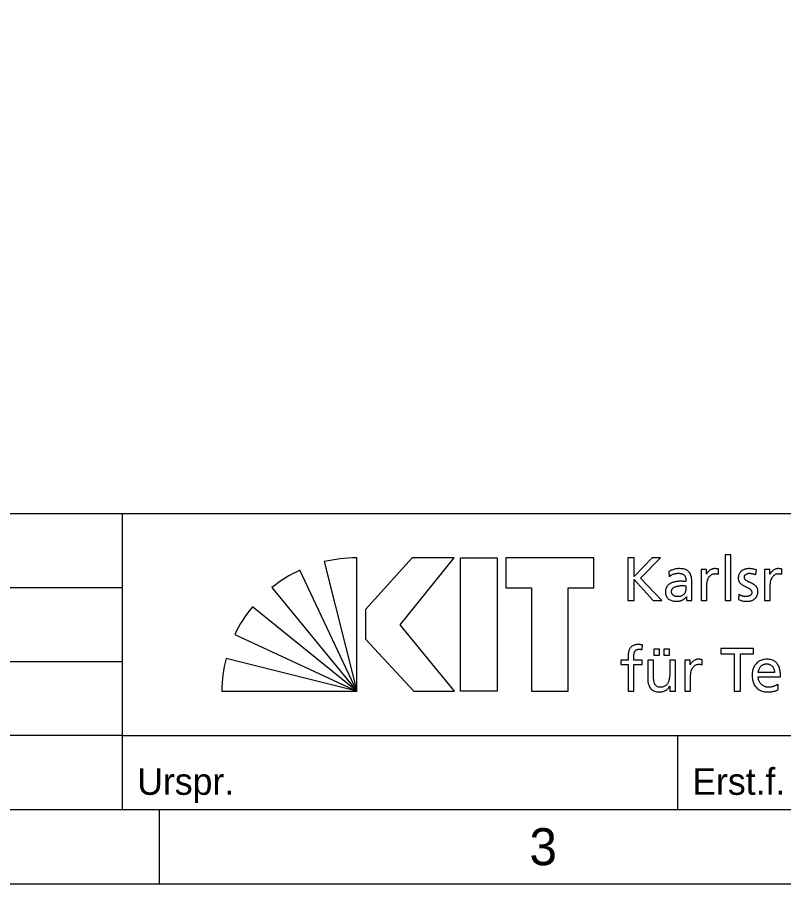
# Model space of a CAD drawing. Extents: x 0 to 420, y 0 to 297.
# Drawn here: x 97.9 to 149.7, y 0 to 58.5 of the extents above; entities that cross this region are included whole.
import ezdxf

# ---------------------------------------------------------------- set-up
doc = ezdxf.new("R2010")
doc.units = 0
doc.layers.add('90_Plankopf', color=7, linetype='Continuous')

msp = doc.modelspace()

# ---------------------------------------------------------------- linework, layer by layer
at = {"layer": '90_Plankopf'}
for p, q in [((5, 25), (415, 25)), ((105, 5), (105, 25)), ((118.621, 21.747), (120.828, 13.001)), ((120.828, 13.001), (120.828, 21.999)), ((139.156, 22.001), (139.156, 19.12)), ((120.828, 13.001), (116.98, 21.167)), ((141.926, 21.076), (141.947, 20.746)), ((145.273, 20.899), (145.273, 21.245)), ((147.804, 20.853), (147.837, 21.192)), ((149.558, 20.899), (149.558, 21.245)), ((5, 20), (105, 20)), ((115.091, 20), (120.828, 13.001)), ((143.077, 20.123), (143.077, 19.937)), ((143.465, 19.533), (143.465, 20.404)), ((146.644, 19.533), (146.624, 19.186)), ((139.156, 19.12), (139.569, 19.12)), ((140.852, 19.12), (141.455, 19.12)), ((120.828, 13.001), (113.78, 18.7)), ((112.587, 16.828), (120.828, 13.001)), ((140.12, 15.807), (140.137, 16.121)), ((5, 15), (105, 15)), ((120.828, 13.001), (112.004, 15.202)), ((144.174, 14.779), (144.174, 15.126)), ((149.053, 14.255), (147.963, 14.255)), ((147.963, 13.967), (149.466, 13.967)), ((149.304, 13.088), (149.304, 13.475)), ((111.711, 13.001), (120.828, 13.001)), ((105, 10), (5, 10)), ((105, 10), (225, 10)), ((142.5, 10), (142.5, 5)), ((107.5, 0), (107.5, 5))]:
    msp.add_line(p, q, dxfattribs=at)
for points in [[(0, 0), (420, 0), (420, 297), (0, 297)], [(5, 5), (415, 5), (415, 292), (5, 292)], [(127.413, 22.001), (124.583, 22.001), (121.42, 18.513), (121.42, 16.506), (124.685, 13.001), (127.432, 13.001), (123.769, 17.477)], [(130.317, 22.001), (130.317, 13.001), (127.848, 13.001), (127.848, 22.001)], [(130.909, 22.001), (130.909, 19.975), (132.648, 19.975), (132.648, 13.001), (135.118, 13.001), (135.118, 19.975), (136.856, 19.975), (136.856, 22.001)]]:
    msp.add_lwpolyline(points, close=True, dxfattribs=at)
for points in [[(141.455, 19.12), (139.994, 20.639), (141.348, 22.001), (140.799, 22.001), (139.569, 20.734), (139.569, 22.001), (139.156, 22.001)], [(145.728, 19.12), (146.115, 19.12), (146.115, 22.215), (145.728, 22.215), (145.728, 19.12)], [(144.469, 20.899), (144.46, 20.899), (144.46, 21.225), (144.097, 21.225), (144.097, 19.12), (144.485, 19.12), (144.485, 20.078)], [(148.754, 20.899), (148.745, 20.899), (148.745, 21.225), (148.382, 21.225), (148.382, 19.12), (148.77, 19.12), (148.77, 20.078)], [(139.569, 19.12), (139.569, 20.532), (140.852, 19.12)], [(143.11, 19.393), (143.118, 19.393), (143.118, 19.12), (143.482, 19.12)], [(140.901, 15.84), (140.901, 15.427), (141.289, 15.427), (141.289, 15.84), (140.901, 15.84)], [(141.578, 15.84), (141.578, 15.427), (141.966, 15.427), (141.966, 15.84), (141.578, 15.84)], [(146.337, 13.001), (146.75, 13.001), (146.75, 15.518), (147.645, 15.518), (147.645, 15.881), (145.441, 15.881), (145.441, 15.518), (146.337, 15.518), (146.337, 13.001)], [(139.171, 15.3), (139.171, 15.105), (138.676, 15.105), (138.676, 14.792), (139.171, 14.792), (139.171, 13.001), (139.559, 13.001), (139.559, 14.792), (140.116, 14.792), (140.116, 15.105), (139.559, 15.105), (139.559, 15.332)], [(140.889, 14.016), (140.889, 15.105), (140.5, 15.105), (140.5, 13.855)], [(142.362, 13.001), (142.362, 15.105), (141.974, 15.105), (141.974, 14.132)], [(143.369, 14.779), (143.361, 14.779), (143.361, 15.105), (142.998, 15.105), (142.998, 13.001), (143.386, 13.001), (143.386, 13.958)], [(141.978, 13.335), (141.986, 13.335), (141.986, 13.001), (142.362, 13.001)]]:
    msp.add_lwpolyline(points, dxfattribs=at)
for centre, start, end in [((120.795, 12.471), 89.80527, 103.18947), ((121.008, 12.532), 115.01261, 128.3968), ((121.163, 12.677), 140.78977, 154.17397), ((121.238, 12.852), 165.72225, 179.10644)]:
    msp.add_arc(centre, 9.528, start, end, dxfattribs=at)
for points in [[(143.465, 20.404), (143.466, 20.595), (143.437, 20.755), (143.38, 20.884), (143.322, 21.014), (143.231, 21.111), (143.106, 21.176), (142.982, 21.241), (142.819, 21.274), (142.619, 21.274), (142.485, 21.274), (142.361, 21.255), (142.244, 21.219), (142.129, 21.183), (142.023, 21.135), (141.926, 21.076)], [(145.273, 21.245), (145.246, 21.251), (145.22, 21.256), (145.196, 21.261), (145.171, 21.265), (145.145, 21.268), (145.116, 21.27), (145.088, 21.273), (145.055, 21.274), (145.017, 21.274), (144.942, 21.274), (144.869, 21.258), (144.799, 21.226), (144.728, 21.194), (144.664, 21.15), (144.607, 21.093), (144.55, 21.037), (144.503, 20.972), (144.469, 20.899)], [(147.837, 21.192), (147.761, 21.215), (147.684, 21.235), (147.606, 21.25), (147.528, 21.266), (147.444, 21.274), (147.354, 21.274), (147.249, 21.274), (147.152, 21.261), (147.062, 21.235), (146.972, 21.208), (146.894, 21.168), (146.826, 21.115), (146.759, 21.061), (146.706, 20.994), (146.669, 20.913), (146.631, 20.831), (146.612, 20.736), (146.611, 20.627), (146.612, 20.543), (146.629, 20.47), (146.662, 20.408), (146.694, 20.347), (146.738, 20.294), (146.792, 20.249), (146.846, 20.204), (146.906, 20.164), (146.97, 20.129), (147.035, 20.095), (147.1, 20.062), (147.164, 20.031), (147.229, 20.001), (147.289, 19.969), (147.342, 19.936), (147.397, 19.905), (147.44, 19.868), (147.473, 19.827), (147.505, 19.787), (147.523, 19.74), (147.523, 19.686), (147.523, 19.629), (147.51, 19.582), (147.486, 19.542), (147.463, 19.504), (147.431, 19.473), (147.392, 19.45), (147.353, 19.426), (147.31, 19.41), (147.264, 19.4), (147.218, 19.389), (147.172, 19.384), (147.127, 19.384), (147.089, 19.384), (147.042, 19.39), (146.986, 19.401), (146.93, 19.412), (146.873, 19.428), (146.813, 19.45), (146.752, 19.472), (146.696, 19.5), (146.644, 19.533)], [(149.558, 21.245), (149.531, 21.251), (149.505, 21.256), (149.481, 21.261), (149.456, 21.265), (149.429, 21.268), (149.401, 21.27), (149.373, 21.273), (149.34, 21.274), (149.302, 21.274), (149.227, 21.274), (149.154, 21.258), (149.084, 21.226), (149.013, 21.194), (148.949, 21.15), (148.892, 21.093), (148.835, 21.037), (148.789, 20.972), (148.754, 20.899)], [(141.947, 20.746), (141.999, 20.79), (142.059, 20.829), (142.126, 20.86), (142.193, 20.893), (142.263, 20.917), (142.336, 20.935), (142.41, 20.952), (142.484, 20.961), (142.557, 20.961), (142.686, 20.961), (142.788, 20.94), (142.865, 20.9), (142.941, 20.858), (142.995, 20.797), (143.028, 20.716), (143.062, 20.634), (143.078, 20.533), (143.077, 20.412)], [(144.485, 20.078), (144.486, 20.254), (144.51, 20.407), (144.556, 20.535), (144.604, 20.663), (144.67, 20.762), (144.756, 20.831), (144.841, 20.9), (144.942, 20.935), (145.058, 20.936), (145.092, 20.936), (145.127, 20.934), (145.164, 20.928), (145.202, 20.923), (145.237, 20.913), (145.273, 20.899)], [(146.624, 19.186), (146.713, 19.14), (146.807, 19.109), (146.905, 19.093), (147.002, 19.077), (147.101, 19.069), (147.201, 19.071), (147.296, 19.071), (147.387, 19.084), (147.474, 19.11), (147.562, 19.136), (147.64, 19.177), (147.71, 19.23), (147.778, 19.284), (147.833, 19.352), (147.874, 19.435), (147.915, 19.517), (147.935, 19.615), (147.936, 19.727), (147.935, 19.822), (147.918, 19.904), (147.886, 19.97), (147.853, 20.037), (147.809, 20.093), (147.755, 20.14), (147.701, 20.186), (147.642, 20.225), (147.577, 20.259), (147.512, 20.292), (147.447, 20.323), (147.383, 20.351), (147.318, 20.38), (147.258, 20.41), (147.205, 20.441), (147.15, 20.473), (147.107, 20.509), (147.074, 20.551), (147.042, 20.593), (147.025, 20.644), (147.024, 20.705), (147.025, 20.763), (147.042, 20.811), (147.076, 20.849), (147.11, 20.886), (147.155, 20.915), (147.211, 20.933), (147.267, 20.952), (147.329, 20.961), (147.395, 20.961), (147.419, 20.961), (147.449, 20.957), (147.485, 20.952), (147.522, 20.945), (147.56, 20.937), (147.601, 20.927), (147.642, 20.917), (147.68, 20.906), (147.716, 20.893), (147.752, 20.88), (147.781, 20.867), (147.804, 20.853)], [(148.77, 20.078), (148.771, 20.254), (148.795, 20.407), (148.841, 20.535), (148.889, 20.663), (148.955, 20.762), (149.041, 20.831), (149.126, 20.9), (149.227, 20.935), (149.344, 20.936), (149.377, 20.936), (149.412, 20.934), (149.449, 20.928), (149.486, 20.923), (149.522, 20.913), (149.558, 20.899)], [(143.077, 20.412), (143.027, 20.415), (142.98, 20.417), (142.936, 20.417), (142.893, 20.419), (142.849, 20.42), (142.806, 20.42), (142.762, 20.42), (142.715, 20.42), (142.664, 20.42), (142.583, 20.42), (142.498, 20.413), (142.409, 20.399), (142.32, 20.384), (142.233, 20.361), (142.147, 20.328), (142.062, 20.296), (141.985, 20.253), (141.915, 20.199), (141.846, 20.146), (141.791, 20.08), (141.75, 20.002), (141.709, 19.924), (141.688, 19.832), (141.686, 19.727), (141.688, 19.575), (141.721, 19.45), (141.786, 19.353), (141.851, 19.256), (141.941, 19.185), (142.056, 19.139), (142.172, 19.093), (142.306, 19.071), (142.458, 19.071), (142.547, 19.071), (142.627, 19.082), (142.697, 19.103), (142.768, 19.124), (142.83, 19.15), (142.883, 19.183), (142.937, 19.216), (142.982, 19.252), (143.02, 19.288), (143.057, 19.325), (143.087, 19.359), (143.11, 19.393)], [(143.077, 19.937), (143.077, 19.832), (143.055, 19.737), (143.01, 19.655), (142.967, 19.571), (142.9, 19.506), (142.814, 19.458), (142.727, 19.41), (142.619, 19.385), (142.491, 19.384), (142.447, 19.384), (142.401, 19.392), (142.355, 19.406), (142.31, 19.421), (142.267, 19.443), (142.229, 19.472), (142.19, 19.501), (142.159, 19.537), (142.136, 19.579), (142.112, 19.622), (142.1, 19.671), (142.099, 19.727), (142.101, 19.8), (142.119, 19.862), (142.155, 19.912), (142.191, 19.961), (142.238, 20), (142.296, 20.029), (142.354, 20.059), (142.416, 20.081), (142.482, 20.096), (142.548, 20.11), (142.612, 20.12), (142.673, 20.125), (142.734, 20.13), (142.786, 20.132), (142.83, 20.131), (142.871, 20.131), (142.912, 20.13), (142.953, 20.127), (142.995, 20.125), (143.036, 20.124), (143.077, 20.123)], [(143.482, 19.12), (143.479, 19.14), (143.476, 19.168), (143.473, 19.201), (143.471, 19.236), (143.469, 19.28), (143.468, 19.334), (143.466, 19.387), (143.465, 19.454), (143.465, 19.533)], [(140.137, 16.121), (140.098, 16.127), (140.057, 16.133), (140.014, 16.138), (139.972, 16.143), (139.926, 16.146), (139.877, 16.146), (139.735, 16.145), (139.617, 16.125), (139.525, 16.085), (139.433, 16.046), (139.361, 15.989), (139.309, 15.914), (139.257, 15.84), (139.221, 15.751), (139.201, 15.647), (139.18, 15.544), (139.171, 15.428), (139.171, 15.3)], [(139.559, 15.332), (139.559, 15.404), (139.563, 15.47), (139.571, 15.531), (139.579, 15.591), (139.596, 15.644), (139.622, 15.689), (139.647, 15.734), (139.685, 15.769), (139.735, 15.794), (139.785, 15.819), (139.851, 15.832), (139.935, 15.832), (139.968, 15.832), (140.002, 15.83), (140.035, 15.825), (140.069, 15.821), (140.097, 15.815), (140.12, 15.807)], [(144.174, 15.126), (144.147, 15.132), (144.121, 15.136), (144.097, 15.141), (144.072, 15.145), (144.045, 15.149), (144.017, 15.151), (143.989, 15.154), (143.956, 15.155), (143.918, 15.155), (143.843, 15.154), (143.77, 15.138), (143.699, 15.106), (143.629, 15.074), (143.565, 15.031), (143.508, 14.974), (143.45, 14.918), (143.404, 14.853), (143.369, 14.779)], [(143.386, 13.958), (143.386, 14.135), (143.41, 14.288), (143.457, 14.416), (143.505, 14.544), (143.571, 14.643), (143.656, 14.711), (143.742, 14.781), (143.843, 14.816), (143.959, 14.816), (143.993, 14.817), (144.028, 14.815), (144.065, 14.809), (144.102, 14.804), (144.138, 14.794), (144.174, 14.779)], [(149.466, 13.967), (149.466, 14.136), (149.45, 14.294), (149.419, 14.438), (149.388, 14.582), (149.336, 14.707), (149.265, 14.815), (149.192, 14.922), (149.097, 15.005), (148.978, 15.064), (148.859, 15.124), (148.711, 15.154), (148.537, 15.155), (148.388, 15.154), (148.253, 15.128), (148.132, 15.077), (148.011, 15.024), (147.907, 14.951), (147.821, 14.856), (147.734, 14.762), (147.668, 14.65), (147.621, 14.519), (147.575, 14.39), (147.551, 14.247), (147.55, 14.09), (147.55, 13.918), (147.572, 13.763), (147.616, 13.623), (147.659, 13.483), (147.726, 13.364), (147.815, 13.264), (147.905, 13.164), (148.018, 13.087), (148.155, 13.033), (148.292, 12.979), (148.454, 12.952), (148.64, 12.951), (148.755, 12.952), (148.853, 12.96), (148.934, 12.975), (149.014, 12.99), (149.084, 13.008), (149.144, 13.028), (149.202, 13.049), (149.256, 13.069), (149.304, 13.088)], [(147.963, 14.255), (147.97, 14.324), (147.986, 14.393), (148.011, 14.462), (148.035, 14.53), (148.069, 14.593), (148.114, 14.651), (148.159, 14.708), (148.216, 14.753), (148.284, 14.788), (148.352, 14.823), (148.434, 14.841), (148.528, 14.841), (148.612, 14.841), (148.687, 14.825), (148.751, 14.795), (148.817, 14.765), (148.871, 14.723), (148.916, 14.669), (148.961, 14.616), (148.995, 14.553), (149.018, 14.483), (149.041, 14.412), (149.053, 14.337), (149.053, 14.255)], [(141.974, 14.132), (141.974, 14.003), (141.962, 13.886), (141.936, 13.78), (141.911, 13.674), (141.872, 13.583), (141.82, 13.506), (141.768, 13.429), (141.701, 13.37), (141.62, 13.328), (141.54, 13.286), (141.444, 13.266), (141.334, 13.265), (141.222, 13.272), (141.133, 13.303), (141.068, 13.36), (141.003, 13.416), (140.957, 13.499), (140.929, 13.607), (140.901, 13.716), (140.888, 13.852), (140.889, 14.016)], [(140.5, 13.855), (140.5, 13.666), (140.528, 13.504), (140.584, 13.369), (140.64, 13.235), (140.726, 13.131), (140.842, 13.06), (140.959, 12.988), (141.108, 12.952), (141.289, 12.951), (141.387, 12.952), (141.482, 12.967), (141.572, 12.997), (141.662, 13.028), (141.743, 13.072), (141.813, 13.129), (141.884, 13.186), (141.939, 13.255), (141.978, 13.335)], [(149.304, 13.475), (149.28, 13.455), (149.245, 13.433), (149.199, 13.409), (149.153, 13.385), (149.101, 13.363), (149.041, 13.34), (148.981, 13.318), (148.918, 13.301), (148.853, 13.287), (148.786, 13.273), (148.721, 13.266), (148.656, 13.265), (148.564, 13.266), (148.476, 13.282), (148.393, 13.316), (148.31, 13.349), (148.236, 13.398), (148.172, 13.46), (148.108, 13.522), (148.057, 13.595), (148.02, 13.681), (147.983, 13.767), (147.964, 13.862), (147.963, 13.967)]]:
    msp.add_open_spline(points, degree=3, dxfattribs=at)

# ---------------------------------------------------------------- texts
for s, height, p in [('Urspr.', 1.8, (106, 6)), ('Erst.f.', 1.8, (143.5, 6)), ('3', 2.5, (132.5, 1.25))]:
    msp.add_text(s, height=height, dxfattribs=at).set_placement(p)

doc.saveas('drawing.dxf')
